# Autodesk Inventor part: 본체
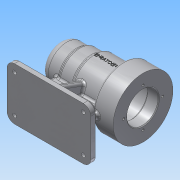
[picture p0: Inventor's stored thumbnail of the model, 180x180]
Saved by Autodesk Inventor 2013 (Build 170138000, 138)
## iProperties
Created: 2016-06
Part Number: 본체
Material: 알루미늄 6061
Document SubType Name: Modeling
Designer: Administrator
Density: 2.71 g/cm^3
Mass: 777.873 g
Surface Area: 688.973 cm^2
Volume: 287.038 cm^3
Author: Administrator
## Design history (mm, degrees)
sketch "스케치1"
  geometry: L1 (-56, 0)-(56, 0); L2 (-56, 0)-(-56, 25); L3 (-56, 25)-(-31, 25); L4 (-31, 25)-(-31, 27); L5 (-11, 27)-(-11, 30); L6 (28, 40)-(56, 40); L7 (56, 40)-(56, 0); L8 (-31, 27)-(-11, 27); L9 (-11, 30)-(-11, 30); L10 (-11, 30)-(28, 30); L11 (28, 30)-(28, 40); L12 (28, 40)-(28, 40); 2 further points
  constraints: 24 end point, 6 parallel, 5 perpendicular, 1 coincident, 1 horizontal, 1 midpoint
  dimensions: "d0" = 112 distance of L1.start L1.end; "d2" = 25 distance between parallel lines of L4 L2; "d3" = 50 diameter of L3 L1; "d9" = 80 diameter of L6 L1; "d11" = 45 distance between parallel lines of L9 L2; "d12" = 84 distance between parallel lines of L11 L2; "d13" = 60 diameter of L10 L1; "d14" = 54 diameter of L8 L1
revolve "회전1" sketch "스케치1" stored, may be unused: angle "d15" = 90 deg
sketch "스케치2"
  geometry: L1 (-56, -25)-(-56, 25) reference; L2 (-56, 25)-(-31, 25) reference; L3 (-31, 25)-(-31, 27) reference; L4 (-31, 27)-(-11, 27) reference; L5 (-11, 27)-(-11, 30) reference; L6 (-11, 30)-(28, 30) reference; L7 (28, 30)-(28, 40) reference; L8 (28, 40)-(56, 40) reference; L9 (56, 40)-(56, -40) reference; L10 (56, -40)-(28, -40) reference; L11 (28, -40)-(28, -30) reference; L12 (28, -30)-(-11, -30) reference; L13 (-11, -30)-(-11, -27) reference; L14 (-11, -27)-(-31, -27) reference; L15 (-31, -27)-(-31, -25) reference; L16 (-31, -25)-(-56, -25) reference; L17 (56, 0)-(-47, 0); L18 (56, 0)-(56, 21); L19 (56, 21)-(41, 21); L20 (41, 21)-(41, 24); L21 (41, 24)-(-13, 24); L22 (-13, 21)-(-25, 21); L23 (-13, 24)-(-13, 21); L24 (-25, 21)-(-25, 17.5); L25 (-47, 16)-(-47, 0); L26 (-25, 17.5)-(-43, 17.5); L27 (-43, 17.5)-(-43, 16); L28 (-43, 16)-(-47, 16); 1 further point
  constraints: 24 end point, 6 perpendicular, 3 parallel, 1 horizontal, 1 midpoint, 1 point on line
  dimensions: "d17" = 103 distance of L17.start L17.end; "d18" = 15 distance between parallel lines of L20 L18; "d19" = 42 diameter of L19 L17; "d20" = 54 distance between parallel lines of L23 L20; "d21" = 48 diameter of L21 L17; "d22" = 12 distance between parallel lines of L23 L24; "d23" = 42 diameter of L22 L17; "d24" = 18 distance between parallel lines of L24 L27; "d25" = 35 diameter of L26 L17; "d26" = 32 diameter of L28 L17
revolve "회전2" sketch "스케치2" stored, may be unused: angle "d27" = 90 deg
sketch "스케치3"
  geometry: L1 (-56, -25)-(-56, 25) reference; L2 (-56, 25)-(-31, 25) reference; L3 (-31, 25)-(-31, 27) reference; L4 (-31, 27)-(-11, 27) reference; L5 (-11, 27)-(-11, 30) reference; L6 (-11, 30)-(28, 30) reference; L7 (28, 30)-(28, 40) reference; L8 (28, 40)-(56, 40) reference; L9 (56, 40)-(56, 21) reference; L10 (56, 21)-(41, 21) reference; L11 (41, 21)-(41, 24) reference; L12 (41, 24)-(-13, 24) reference; L13 (-13, 24)-(-13, 21) reference; L14 (-13, 21)-(-25, 21) reference; L15 (-25, 21)-(-25, 17.5) reference; L16 (-25, 17.5)-(-43, 17.5) reference; L17 (-43, 17.5)-(-43, 16) reference; L18 (-43, 16)-(-47, 16) reference; L19 (-47, 16)-(-47, -16) reference; L20 (-47, -16)-(-43, -16) reference; L21 (-43, -16)-(-43, -17.5) reference; L22 (-43, -17.5)-(-25, -17.5) reference; L23 (-25, -17.5)-(-25, -21) reference; L24 (-25, -21)-(-13, -21) reference; L25 (-13, -21)-(-13, -24) reference; L26 (-13, -24)-(41, -24) reference; L27 (41, -24)-(41, -21) reference; L28 (41, -21)-(56, -21) reference; L29 (56, -21)-(56, -40) reference; L30 (56, -40)-(28, -40) reference; L31 (28, -40)-(28, -30) reference; L32 (28, -30)-(-11, -30) reference; L33 (-11, -30)-(-11, -27) reference; L34 (-11, -27)-(-31, -27) reference; L35 (-31, -27)-(-31, -25) reference; L36 (-31, -25)-(-56, -25) reference; L37 (-47, 0)-(-53, 0); L38 (-53, 0)-(-53, 10.5); L39 (-53, 10.5)-(-47, 10.5); 1 further point
  constraints: 6 end point, 2 perpendicular, 1 midpoint, 1 parallel, 1 point on line
  dimensions: "d28" = 3 distance between parallel lines of L38 L1; "d29" = 21 diameter of L39 L37
revolve "회전3" sketch "스케치3" stored, may be unused: angle "d30" = 90 deg
chamfer "모따기1" distance "d33" = 1; stored, may be unused: second distance "d34" = 2, angle "d35" = 45 deg
sketch "스케치4"
  geometry: L1 (0, 0)-(0, 26); C1 r 22 at (0, 0) reference; 1 further point
  constraints: 2 end point, 1 coincident, 1 vertical
  dimensions: "d36" = 26 distance of L1.start L1.end
hole "구멍1" sketch "스케치4" at (0, 26) diameter "d37" = 3.242; stored, may be unused: countersink angle "d41" = 90 deg, drill point angle "d43" = 118 deg; dims "d38" = 8, "d39" = 4, "d40" = 2, "d42" = 11
node "작업 평면1"
sketch "스케치5"
  geometry: L1 (56, -35)-(-56, -35); L2 (-56, -35)-(-56, 35); L3 (-56, 35)-(56, 35); L4 (56, 35)-(56, -35); L5 (56, -35)-(-56, 35); L6 (-56, -35)-(56, 35); 3 further points
  constraints: 12 end point, 3 midpoint, 2 parallel, 1 coincident, 1 horizontal, 1 perpendicular
  dimensions: "d48" = 112 distance of L2.end L3.end; "d49" = 70 distance of L1.end L2.end
extrude "돌출1" join sketch "스케치5" distance "d50" = 10; taper "d51" = 0 deg
sketch "스케치6"
  geometry: L1 (-56, 35)-(-56, -35) reference; L2 (36, -4)-(-36, -4); L3 (-36, -4)-(-36, 4); L4 (-36, 4)-(36, 4); L5 (36, 4)-(36, -4); L6 (36, -4)-(-36, 4); L7 (-36, -4)-(36, 4); L8 (4, -28)-(-4, -28); L9 (-4, -28)-(-4, 28); L10 (-4, 28)-(4, 28); L11 (4, 28)-(4, -28); L12 (4, -28)-(-4, 28); L13 (-4, -28)-(4, 28); L14 (56, 35)-(56, -35) reference; L15 (56, -35)-(-56, -35) reference; L16 (-56, -35)-(-56, 35) reference; L17 (-56, 35)-(56, 35) reference; 1 further point
  constraints: 24 end point, 4 midpoint, 4 parallel, 2 horizontal, 2 perpendicular
  dimensions: "d52" = 8 distance of L2.end L3.end; "d53" = 8 distance of L9.end L10.end; "d54" = 20 distance between parallel lines of L3 L1; "d55" = 7 distance between parallel lines of L10 L17
extrude "돌출2" join sketch "스케치6" stored distance "d56" = 10; taper "d57" = 0 deg
feature "면 기울기1" dims angle "d58" = 20 deg
fillet "모깎기3" dims "d59" = 10
fillet "모깎기4" dims "d60" = 3
fillet "모깎기5" dims "d61" = 3
fillet "모깎기8" dims "d64" = 3
fillet "모깎기10" dims "d66" = 3
sketch "스케치7"
  geometry: A1 r 7 centre (-46, 25) between (-46, 32) and (-53, 25) reference; A2 r 7 centre (-46, -25) between (-53, -25) and (-46, -32) reference; A3 r 7 centre (46, -25) between (46, -32) and (53, -25) reference; A4 r 7 centre (46, 25) between (53, 25) and (46, 32) reference; 5 further points
  constraints: 4 coincident
hole "구멍2" sketch "스케치7" at (-46, 25), (-46, -25), (46, 25), (46, -25) diameter "d67" = 5; stored, may be unused: countersink angle "d71" = 90 deg, drill point angle "d73" = 118 deg; dims "d68" = 5, "d69" = 9, "d70" = 4, "d72" = 11
node "작업 평면2"
fillet "모깎기11" dims "d78" = 3
node "작업 평면3"
sketch "스케치9"
  geometry: L1 (56, 1.621)-(56, -1.621) reference; 2 further points
  constraints: 1 horizontal alignment, 1 other
  dimensions: "d80" = 48 distance from line of point (8, 0) L1
feature "엠보싱2" sketch "스케치9" dims "d81" = 0.5, "d82" = 0
fillet "모깎기12" dims "d83" = 3
fillet "모깎기14" dims "d85" = 3
fillet "모깎기16" dims "d87" = 3
fillet "모깎기17" dims "d88" = 0.3
fillet "모깎기18" dims "d89" = 3
chamfer "모따기2" distance "d90" = 4; stored, may be unused: second distance "d91" = 2, angle "d92" = 45 deg
node "솔리드1"
pattern_circular "원형 패턴1" dims angle "d45" = 360 deg
node "절단 모서리 투영1"
node "절단 모서리 투영2"
node "절단 모서리 투영3"
